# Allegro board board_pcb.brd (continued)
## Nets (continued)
VCC_SYS: C1589.2(B) C1590.1 C1591.1 C1592.1 C1772.1 C1773.2(B) C1880.1 L59.1 Q35.5 Q35.6 Q35.7 Q35.8 R1552.2(B)
VCCD: C1504.2(B) C1505.2(B) U117.24
VDD1V2: C339.2(B) C341.1 C1916.1 LB5.2 U1.N17
VDD_MCU: C197.1 C228.2(B) C229.2(B) C230.2(B) C231.2(B) C271.2(B) C273.2(B) C274.2(B) C282.2(B) C283.2(B) C284.2(B) C285.2(B) C286.2(B) C287.2(B) C288.2(B) C289.2(B) C290.2(B) C342.2(B) C343.2(B) C344.2(B) C345.2(B) C1970.1 C1971.1 C1972.1 C1973.2(B) C1974.2(B) C1975.1 C1976.2(B) C2004.2(B) C2005.2(B) C2006.2(B) C2007.2(B) L63.2 U1.A6 U1.C17 U1.E6 U1.E9 U1.E11 U1.F5 U1.F17 U1.G5 U1.G13 U1.H5 U1.H13 U1.J13 U1.K5 U1.K13 U1.L5 U1.L13 U1.M5 U1.M13 U1.N7 U1.N8 U1.N10 U1.N11 U1.N12 U1.P17 U1.U12
VDD_SDRAM: C1639.2(B) C1818.1 C1819.1 C1820.1 C1821.2(B) C1918.2(B) C1919.2(B) C1920.2(B) C1921.2(B) C1922.2(B) C1923.2(B) C1924.2(B) C1925.2(B) C1926.2(B) C1927.2(B) C1928.2(B) C1929.2(B) C1930.2(B) C1931.2(B) L61.2 U2.A7 U2.B2 U2.B7 U2.C9 U2.D9 U2.E1 U2.F9 U2.L1 U2.L7 U2.M9 U2.N9 U2.P2 U2.P7 U2.R7
VDDA3V3: C1950.1 C1977.1 C1978.2(B) LB8.2 U1.L1
VDDD: C1502.2(B) C1503.2(B) C1506.2(B) R1358.2(B) R1360.2(B) R1368.2(B) R1369.2(B) R1388.2(B) R1389.2(B) R1390.2(B) R1501.1 R1525.1 R1526.1 U117.23(VDDD)
VDDIO3V3_SD: C2001.1 C2002.2(B) LB7.2 U1.F1
AIN_0: J74.3 U134.21
AIN_1: J74.1 U134.20
AIN_2: J74.2 U134.19
BATP: R1519.2(B) R1520.1 R1852.2(B)
BL_KEY: C1910.1 R1744.1 R1856.1 U1.A11 U135.26
BL_REST: C1909.1 R1743.2(B) S6.2 U1.A12 U135.11
BL_RX: R1754.2(B) R1816.1 U135.2
BL_TX: R1753.2(B) R1815.1 U135.1
BOOT0: C1964.1 R1799.1 R1854.1 U1.E8
BOOT1: R1803.1 U1.R6
BQ_AGND: C1653.2(B) C1998.2(B) J85.2 Q39.2(S) R1481.2(B) R1484.2(B) R1500.1 R1503.2(B) R1518.1 R1523.1 R1738.2(B) U133.10 U133.11
BQ_CE_N: R1500.2(B) R1866.2(B) U133.13
BQ_DN: R1510.1 U133.7
BQ_DP: R1510.2(B) U133.6
BQ_INT: R1508.2(B) R1733.2(B) U1.D3
BQ_QON_N: Q39.3 U133.12
BQ_REGN: C1640.1 R1483.1 R1516.1 R1867.2(B) U133.5
BQ_STAT: D134.1(K) U133.1
BQ_TS: C1998.1 J85.1 R1516.2(B) R1518.2(B) R1738.1 R1853.2(B)
CC1: C1499.2(B) D107.1(CATHODE) J73.A5 U117.15
CC2: C1507.2(B) D106.1(CATHODE) J73.B5 U117.14
CE_0: J75.3 J76.1 U134.18
CE_1: J76.6 U134.12
CHARGER_QON: Q39.1 R1503.1 U1.D2
DEBUG_MS_RX: D114.1 J78.14 S8.5
DEBUG_MS_TX: D114.2(C2) J78.12 S8.6
ETH_MDC: U1.M2 U3.24
ETH_MDIO: R1776.2(B) U1.N3
ETH_RMII_CLK: R1778.2(B) R1782.2(B) R1783.2(B) X5.3
ETH_RMII_RXD0: R1774.2(B) U1.T4
ETH_RMII_RXD1: R1775.2(B) U1.U4
ETH_RMII_RXDV: R1777.2(B) U1.R5
ETH_RMII_TX_EN: U1.B9 U3.21
ETH_RMII_TXD0: R1787.1 U1.D9
ETH_RMII_TXD1: R1848.1 U1.U14
ETH_RMII_TXD1-1: R1788.1 U1.D8
FAULT: U1.E5 U117.9
FET_GATE: D97.2 Q22.2 Q22.4 R1381.1 R1495.2(B)
FET_SRC: D97.1(CATHODE) Q22.1 Q22.3(S2) R1495.1
FMC_A0: U1.G4 U2.G8
FMC_A1: U1.G3 U2.G9
FMC_A2: U1.G1 U2.F7
FMC_A3: U1.H4 U2.F3
FMC_A4: U1.J5 U2.G1
FMC_A5: U1.J4 U2.G2
FMC_A6: U1.R7 U2.G3
FMC_A7: U1.P7 U2.H1
FMC_A8: U1.P8 U2.H2
FMC_A9: U1.R9 U2.J3
FMC_A10: U1.T8 U2.G7
FMC_A11: U1.U8 U2.H9
FMC_A12: R1851.1 U1.H16
FMC_A14/FMC_BA0: U1.H14 U2.J7
FMC_A15/FMC_BA1: U1.G14 U2.H8
FMC_D0: U1.P16 U2.R8
FMC_D1: U1.P15 U2.N7
FMC_D2: U1.D13 U2.R9
FMC_D3: U1.E12 U2.N8
FMC_D4: U1.U9 U2.P9
FMC_D5: U1.T9 U2.M8
FMC_D6: U1.P9 U2.M7
FMC_D7: U1.N9 U2.L8
FMC_D8: U1.P10 U2.L2
FMC_D9: U1.R10 U2.M3
FMC_D10: U1.T10 U2.M2
FMC_D11: U1.U10 U2.P1
FMC_D12: U1.R11 U2.N2
FMC_D13: U1.U16 U2.R1
FMC_D14: U1.T17 U2.N3
FMC_D15: U1.T16 U2.R2
FMC_D16: U1.T13 U2.E8
FMC_D17: U1.R13 U2.D7
FMC_D18: U1.P13 U2.D8
FMC_D19: U1.P14 U2.B9
FMC_D20: U1.R14 U2.C8
FMC_D21: U1.D16 U2.A9
FMC_D22: U1.B17 U2.C7
FMC_D23: U1.B16 U2.A8
FMC_D24: U1.A16 U2.A2
FMC_D25: U1.A15 U2.C3
FMC_D26: U1.B15 U2.A1
FMC_D27: U1.C14 U2.C2
FMC_D28: U1.A2 U2.B1
FMC_D29: U1.B3 U2.D2
FMC_D30: U1.E2 U2.D3
FMC_D31: U1.F3 U2.E2
FMC_NBL0: U1.C4 U2.K9
FMC_NBL1: U1.B4 U2.K1
FMC_NBL2: U1.A4 U2.F8
FMC_NBL3: U1.A3 U2.F2
FMC_SDCKE0: R1849.1 U1.N2
FMC_SDCLK: U1.F15 U2.J1
FMC_SDNCAS: U1.D6 U2.K7
FMC_SDNE0: R1835.1 U1.P2 U2.J8
FMC_SDNRAS: U1.T7 U2.J9
FMC_SDNWE: U1.P4 U2.K8(W\E\)
GAUGE_ALCC: R1448.1 R1831.2(B) U1.C3
GAUGE_PULLUP: C511.1 C512.1 Q50.3 R1699.2(B) R1700.2(B) R1831.1
GAUGE_SCL: R1450.1 R1699.1 R1813.1
GAUGE_SDA: R1449.1 R1700.1 R1814.1
GPIO_0: J78.5 U134.6
GPIO_1: J78.10 U134.7
GPIO_2: J78.3 U134.9
GPIO_3: J78.1 U134.10
GPIO_4: J78.8 U134.11
GPIO_5: J78.13 U134.22
GPIO_6: J78.15 U134.23
GPIO_7: J78.7 U134.24
I2C1_SCL: R1812.2(B) R1814.2(B) U1.D5
I2C1_SDA: R1811.2(B) R1813.2(B) U1.D4
ISINK_COARSE: R1368.1 R1370.2(B) U117.5
ISINK_FINE: R1367.1 R1369.1 U117.6
JTCK: J6.3 J56.1 R1838.1 R1843.2(B) U1.B14
JTDI: J56.9 R1839.2(B) U1.A14
JTDO: J56.3 R1842.2(B) U1.C6
JTMS: J6.4 J56.5 R1837.2(B) U1.C15
JTRST: R1840.2(B) R1841.1 U1.B7
LCD_B0: J1.21 J2.21 U1.D11
LCD_B1: J1.22 J2.22 U1.E10
LCD_B2: J1.23 J2.23 U1.D10
LCD_B3: J1.24 J2.24 U1.B10
LCD_B4: J1.25 J2.25 U1.C8
LCD_B5: J1.26 J2.26 U1.B8
LCD_B6: J1.27 J2.27 U1.A8
LCD_B7: J1.28 J2.28 U1.C7
LCD_CLK: J1.30 J2.30 U1.H3
LCD_DE: J1.34 J2.34 U1.D7
LCD_G0: J1.13 J2.13 U1.N14
LCD_G1: J1.14 J2.14 U1.N13
LCD_G2: J1.15 J2.15 U1.M14
LCD_G3: J1.16 J2.16 U1.L14
LCD_G4: J1.17 J2.17 U1.K14
LCD_G5: J1.18 J2.18 U1.J14
LCD_G6: J1.19 J2.19 U1.J15
LCD_G7: J1.20 J2.20 U1.H17
LCD_HSYNC: J1.32 J2.32 U1.H1
LCD_PWM: J1.35 J2.35 U1.E15
LCD_R0: J1.5 J2.5 U1.P5
LCD_R1: J1.6 J2.6 U1.N6
LCD_R2: J1.7 J2.7 U1.P6
LCD_R3: J1.8 J2.8 U1.T6
LCD_R4: J1.9 J2.9 U1.U6
LCD_R5: J1.10 J2.10 U1.U7
LCD_R6: J1.11 J2.11 U1.R12
LCD_R7: J1.12 J2.12 U1.N15
LCD_VSYNC: J1.33 J2.33 U1.H2
LED0: D132.1(K) U1.U5
LINKACT2: J3.11 R1785.1 U3.13
MP1_VCC: C1790.2(B) D112.2 R1604.2(B) U8.9
MS_DWN: C185.1 J78.4 R1740.2(B) S3.2 U1.B11 U134.4
MS_I2CSCL: J78.11 R1755.2(B) U134.25
MS_I2CSDA: J78.9 R1756.2(B) U134.26
MS_RST: C1908.1 J78.6 R1741.2(B) S5.2 U1.C11 U134.5
MS_RX: R1752.2(B) S8.2 S8.4 U134.2
MS_TX: R1751.2(B) S8.1 S8.3 U134.3
NRST: C1965.1 J6.5 R1800.2(B) S11.2 U1.K1
OSC32_IN: C433.2(B) U1.C2 X4.1
OSC32_OUT: C432.2(B) U1.C1 X4.2
OSC_IN: C355.2(B) R84.1 U1.J2 X3.1
OSC_OUT: R32.2(B) R84.2(B) U1.J1
PHY_3V3: C1955.2(B) C1956.1 C1957.1 C1958.2(B) C2000.2(B) C2023.2(B) C2024.2(B) C2025.2(B) LB9.2 R1768.2(B) R1769.2(B) R1770.1 R1773.2(B) R1781.2(B) R1784.2(B) R1785.2(B) R1786.2(B) R1790.1 R1791.1 U3.23 U3.30 U3.31 U3.41 X5.4(VCC)
PHY_INT: R946.2(B) U1.T11
PHY_RESET: R1826.1 U1.B12 U3.40(\R\E\S\E\T\)
PMID: C1695.1 C1696.1 C1697.1 C1698.1 U133.29
POWER_KEY: J86.1 R324.2(B) R325.1 S4.1
POWER_OFF: Q36.1 R1554.2(B) U1.R16
PWR_INT_N: R406.1 U1.R15
QUADSPI_BK1_IO0: R1817.2(B) U1.K4 U77.5
QUADSPI_BK1_IO1: R1819.2(B) U1.L4 U77.2
QUADSPI_BK1_IO2: R1820.2(B) U1.K3 U77.3(W#/VPP/DQ2)
QUADSPI_BK1_IO3: R1818.2(B) U1.K2 U77.7
QUADSPI_BK1_NCS: R898.2(B) U1.G15 U77.1
QUADSPI_CLK: U1.L3 U77.6
RE_0: J75.1 J76.3 U134.16
RE_1: J76.8 U134.14
RX1_N: J73.B10
RX1_P: J73.B11
RX2_N: J73.A10
RX2_P: J73.A11
RX+: J3.3 R1795.2(B) U3.3
RX-: J3.6 R1796.2(B) U3.4
SDIO0_CARD_DETECT: J8.9 R118.2(B) U1.C9
SDIO0_CARD_POWER_EN: R116.1 R119.2(B) U1.U3
SDIO0_CCLK_OUT: J8.5 R281.1
SDIO0_CCMD: J8.3 R1221.1
SDIO0_CDATA0: J8.7 R1222.1
SDIO0_CDATA1: J8.8 R1223.1
SDIO0_CDATA2: J8.1 R1224.1
SDIO0_CDATA3: J8.2 R1225.1
SDIO0_VDD_3.3V: C4.1 C43.1 J8.4 Q1.3 R117.1
SPEEDLED2: J3.10 Q18.3
TP_I2C1_SCL: J1.37 J2.37 R1760.2(B) R1812.1
TP_I2C1_SDA: J1.38 J2.38 R1759.2(B) R1811.1
TP_INT: J1.39 J2.39 R1828.2(B) R1830.2(B) U1.U13
TP_RESET: C1980.1 J1.40 J2.40 R1829.1 U1.P3
TX1_N: J73.A3
TX1_P: J73.A2
TX2_N: J73.B3
TX2_P: J73.B2
TX+: J3.1 R1793.2(B) U3.7
TX-: J3.2(TD-) R1794.2(B) U3.8
UART1_RX: D76.1 J63.3 R1626.2(B) U1.C5
UART1_TX: D76.2(C2) J63.2 U1.B5
UART3_RX: R1865.2(B) S8.8 U1.P12
UART3_TX: S8.7(B6) U1.P11
UART4_RX: R1815.2(B) U1.E17
UART4_TX: R1816.2(B) U1.E16
USB3_DM: D108.1(CATHODE) J73.A7 J73.B7 U1.U15
USB3_DP: D109.1(CATHODE) J73.A6 J73.B6 U1.T15
USB_OTG_ID: R1859.2(B) U1.T14
WE_0: J75.5 J76.2 U134.17
WE_1: J76.7 U134.13(WE_1)
N06481: C1509.1 C1575.1 D96.1(CATHODE) F4.2(P2) Q22.7 Q22.8 R1382.1 R1386.1 R1451.2(B) U117.18
N06955: C1521.1 R1451.1
N07169: C1509.2(B) C1510.2(B) R1381.2(B) R1382.2(B) R1383.2(B)
N07181: R1386.2(B) R1387.2(B) TS1.1
N07533: R1387.1 U117.4
N07661: R1383.1 U117.3
N07823: R1389.1 U117.12
N07951: R1388.1 U117.13
N08069: R1390.1 U117.7
N08149: R1501.2(B) U117.8
N08736: Q2.3 R25.2(B)
N08740: Q2.1 R119.1
N08748: C75.2(B) Q1.1 R25.1 R135.2(B)
N14544: C1641.2(B) U133.4
N14548: C1641.1 L54.2 U133.28
N14620: R1448.2(B) U128.6
N14770: R1450.2(B) U128.4
N14904: R1449.2(B) U128.5
N14944: F1.1 R1446.1 R1520.2(B) U128.8(SENSE-)
N15026: C1642.1 L54.1 U133.26
N15146: C1642.2(B) U133.19
N15862: R1852.1 U133.18
N16110: C1653.1 U133.24
N16190: R1483.2(B) R1484.1 U133.17
N16266: R1481.1 U133.20
N17136: R522.2(B) U1.G17
N26661: C1771.2(B) C1774.1 C1775.1 C1776.1 C1777.1 C1778.2(B) L59.2 R85.1 U8.3(VIN#3) U8.15
N27346: C1595.1 C1597.2(B) C1605.1 C1623.1 C1624.2(B) L50.2 R1611.1 U132.2
N29886: Q35.4 R1706.2(B)
N29984: C1880.2(B) R1705.2(B)
N30034: R1468.1 R1705.1 R1706.1
N30108: C1879.1 R1468.2(B) R1469.2(B) U37.3
N30120: C402.1 R1460.2(B) R1461.1 U37.4(VIN)
N30264: R406.2(B) R1373.1 U37.1
N30390: C413.1 R325.2(B) U37.5
N30402: C595.1 Q36.3 R1552.1 R1553.1 U37.9
N30450: C1485.2(B) U37.8
N34682: R14.2(B) R1739.1 U4.3
N51448: R1747.1 U135.24
N51452: D113.2 R1747.2(B)
N56281: C223.2(B) C354.2(B) C1291.1 C2012.1 C2013.1 L43.2 R1749.1 U26.2
N56325: L10.1 U26.3(SW)
N56705: R86.2(B) R1615.1
N56737: R176.1 U26.7
N56741: R176.2(B) R1615.2(B) R1748.1
N57183: R1749.2(B) U26.8
N60036: D117.1(K) R1751.1
N60157: D118.1(K) R1752.1
N61083: D121.1(K) R1755.1
N61087: D122.1(K) R1756.1
N8840853: R1733.1 U133.21
N8856572: C356.2(B) R32.1 X3.3
N8887240: R281.2(B) U1.C12
N8887299: R1224.2(B) U1.A13
N8887317: R1225.2(B) U1.B13
N8887321: R1223.2(B) U1.E14
N8887325: R1222.2(B) U1.E13
N8887398: R1221.2(B) U1.D12
N8915420: C1945.2(B) U1.U11
N8916004: C1947.2(B) U1.A7
N8924132: R1766.1 U3.48
N8924451: R1767.1 U3.38
N8924569: R1768.1 U3.36
N16774766: R946.1 R1769.1 U3.32
N16774923: R1770.2(B) R1774.1 U3.29
N16774927: R1775.1 U3.28
N16775135: R1773.1 R1776.1 U3.25
N16776183: R1777.1 U3.37
N16776304: R1783.1 U3.42
N16776308: R1778.1 U3.43
N16776812: R1781.1 X5.1
N16777866: R1786.1 U3.11
N16777871: Q18.2(EMITTER) R1784.1 U3.12
N16777887: R1855.2(B) U3.14
N16778460: R1787.2(B) U3.20
N16778536: R1788.2(B) R1848.2(B) U3.19
N16779520: Q18.1 R1855.1
N16781751: J3.9 R1790.2(B)
N16781754: J3.12 R1791.2(B)
N16783015: C1961.2(B) R1793.1 R1794.1
N16783029: C1962.2(B) R1795.1 R1796.1
N16791902: R1797.2(B) R1798.2(B) U1.E7
N16792692: R1854.2(B) S10.1
N16792994: R1856.2(B) S7.1
N16847649: R20.2(B) U4.5
N16850956: D133.2 R1806.2(B)
N16850985: D132.2 R1807.2(B)
N16872883: R1782.1 U1.N4
N16886716: C1946.2(B) U1.D17
N16890832: R1853.1 U133.16
N16908117: R1851.2(B) U2.H3
N16908318: R1849.2(B) U2.J2
N16914135: D74.1(K) R1626.1
N16971823: F1.2(P2) J5.1
N16972859: J5.2(-) J7.1
N16973460: C1904.2(B) Q50.1 R1734.1 R1737.2(B)
N16973494: Q10.3 R1734.2(B)
N16973521: C517.1 Q10.1 R1697.1 R1698.1
N17017170: R50.1 R1673.1 U140.4(Y)
N17017201: R1526.2(B) U140.2
N17038390: D134.2 R1867.1 R1868.2(B)
N17048586: C1875.2(B) D25.2(P2) R1695.1 R1696.1
N17051637: R1863.2(B) R1864.1 U141.3
N17051655: R1862.2(B) U141.5
N17071435: R1868.1 R1869.1
N19175875: C1791.2(B) U8.7
N19175881: R1608.2(B) U8.8
N19175893: C1779.1 L60.1 U8.2 U8.11
N19175909: R1605.1 U8.6
N19176042: R1602.1 R1604.1 U8.5
N19176179: R1599.1 U8.10
N19176181: C1779.2(B) D112.1(K) R1599.2(B)
N19179790: R1608.1 R1609.1
N19180483: C1789.1 R1605.2(B) R1606.1 R1607.1
N19180998: C1789.2(B) R1603.2(B)
N19211433: R85.2(B) R142.1 U8.4
N19540928: R1607.2(B) R1610.1
N19572988: R1611.2(B) U132.8
N19573026: L53.1 U132.3(SW)
N19573046: R1477.1 U132.7
N19573048: R1475.1 R1477.2(B) R1613.1
N19576360: R1612.2(B) R1613.2(B)
N88478500: R1742.1 S5.1
N88479500: R267.1 S3.1
N88497910: R1745.1 S6.1
N167922400: R1802.1 S11.1

Pads without a net: J3 7; J6 6; J56 6 7 8; J73 A8 B8; J75 4; M4 1; NOREF#4 1; NOREF#6 1; NOREF#10 1; NOREF#15 1; NOREF#17 1; NOREF#18 1; U1 A5 A9 A10 D1 D14 D15 E1 E3 E4 F4 F13 F14 F16 H15 K16 K17 L2 L16 L17 M3 M4 M16 M17 N5 R1 R2 R3 R17 T1 T2 T3 T5 U2; U2 E3 E7 H7 K2 K3; U3 16 17 18 22 26 27 34 35 45; U4 6; U26 1; U37 2; U117 10 16 17 20 21; U132 1; U133 14 15; U134 1; U135 3 4 5 6 7 8 9 10 14 15 16 17 18 19 20 21 22 23 25 27 28 29 30 31 32 33 34; U140 1; U141 6

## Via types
v1: diameter 0.559, hole 0.254, TOP to BOTTOM, 1326 vias
v2: diameter 0.406, hole 0.203, TOP to BOTTOM, 328 vias

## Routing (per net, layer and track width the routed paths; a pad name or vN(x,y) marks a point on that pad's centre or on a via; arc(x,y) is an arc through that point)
1V2: length 12.3
  TOP w0.305: U26.5 v1(80,55.37) ; R86.1 78.87,60.1 78.87,62.03 80.59,63.75 v1(81.03,63.75)
  BOTTOM w0.305: v1(80,55.37) 80.64,56.01 82.93,56.01 83.82,56.9 v1(83.82,58.17)
  vias: v1(59.44,75.82) v1(60.2,75.82) v1(60.96,75.82) v1(82.55,63.75) v1(83.82,63.75) v1(83.82,62.48) v1(83.82,61.21)
2V5: length 7.2
  TOP w0.305: v2(54.48,56.01) 54.48,56.13 54.47,56.15 U1.M1
  BOTTOM w0.305: v1(57.28,44.58) 55.85,44.58 R1863.1 ; v2(54.48,56.01) 54.78,55.71 C1952.2 C1951.1 54.36,54.36 54.23,54.48 53.87,54.48 53.85,54.46 v1(53.85,53.72) v1(53.85,52.96)
  vias: v1(57.28,45.47)
3V3: length 85.7
  TOP w0.305: R1759.1 v1(94.74,103) ; R1840.1 40.01,61.98 38.86,60.83 38.86,59.69 v1(39.62,58.93) R1797.1 ; R1817.1 50.93,52.7 v1(51.31,53.09) ; D118.2 v1(32.51,49.91) ; v1(60.71,46.35) 60.02,46.35 58.55,44.88 58.55,41.3 R1612.1 ; D74.2 v1(29.84,11.3) ; D121.2 30.68,35.84 30.99,36.14 v1(30.99,36.47) 31.11,36.6 31.11,39.24 30.1,40.26 D122.2 ; C1904.1 76.96,7.47 R1806.1 ; R1508.1 v1(57.28,15.37) ; 64.14,48.64 63.63,49.15 R1819.1 R1820.1 ; R1753.1 v1(64.9,104.01) ; R1740.1 v1(15.37,65.91) ; D117.2 v1(32.51,51.56) ; R118.1 v1(45.87,89.79) ; R1843.1 v1(50.29,97.16) ; v1(73.79,18.92) 73.94,19.08 R1373.2 ; R1743.1 v1(57.81,90.58) ; R1754.1 v1(64.9,99.69) ; R1837.1 v1(54.99,95.38) ; S10.2 v1(48.56,90.76) ; R1760.1 v1(94.74,101.85) ; C915.1 51.33,47.52 v1(51.69,47.88) ; R1807.1 69.09,47.75 ; D25.1 36.32,49.4 36.04,49.12 C1999.1 36.04,48.16 v1(36.58,47.62) ; v1(52.83,20.19) 53.06,20.42 R1866.1 ; R1741.1 v1(24,65.91) ; R1865.1 29.44,64.16 v1(29.72,63.88) ; R1828.1 v1(85.32,100.23) ; R1800.1 v1(52.96,91.44) ; v1(51.69,47.88) U77.8 ; v1(51.69,47.88) 51.69,47.98 R1818.1 ; R1839.1 v1(57.15,95.38) ; R1842.1 v1(53.34,95.38) ; S7.2 v1(87.25,81.2)
  ART06 w0.508: v1(52.83,20.19) 56.01,17.02 57.02,17.02
  BOTTOM w0.305: 63.25,47.62 63.25,48.44 62.79,48.9 62.79,54.31 64.77,56.29 64.77,62.64 R1835.2 ; LB7.1 46.49,54.36 v1(46.35,54.36) 47.24,53.47 49.64,53.47 LB8.1 50.79,52.57 v1(51.31,53.09) ; R1862.1 58.04,37.47
  vias: v1(5.33,61.09) v1(6.35,61.09) v1(7.49,61.09) v1(7.62,69.47) v1(7.62,68.45) v1(8.64,69.47) v1(8.64,68.45) v1(35.81,9.78) v1(35.81,8.89) v1(36.83,9.78) v1(36.83,8.89) v1(40.13,43.18) v1(40.13,42.42) v1(43.41,90.83) v1(44.2,90.81) v1(49.02,103.5) v1(49.02,102.49) v1(56.64,32.51) v1(57.91,33.91) v1(58.55,35.81) v1(59.31,36.58) v1(60.07,36.58) v1(62.23,46.35) v1(62.61,38.61) v1(63.25,37.21) v1(63.37,87.12) v1(63.37,86.11) v1(63.5,46.35) v1(63.5,45.09) v1(63.5,43.81) v1(63.5,38.61) v1(64.77,46.35) v1(64.77,45.09) v1(64.77,43.81) v1(71.63,47.12) v1(71.63,45.97) v1(71.63,44.7) v1(77.22,6.35) v1(77.22,5.33) v1(78.23,6.35) v1(78.23,5.33)
5V0: length 31.7
  TOP w0.305: R1830.1 v1(85.32,102.87) ; 75.18,45.47 74.93,45.72 74.93,48.39 75.44,48.9 90.17,48.9 93.34,45.72 93.34,41.91 92.94,41.5 R1603.1 92.94,40.39 R1606.2 ; R50.2 42.85,42.47 v1(42.55,42.16) ; R20.1 31.75,34.92 v1(32.13,34.54)
  vias: v1(30.99,34.54) v1(30.99,33.4) v1(32.13,33.4) v1(72.52,37.97) v1(72.52,36.7) v1(73.66,37.97) v1(73.66,36.7) v1(75.18,44.7) v1(75.18,43.69) v1(75.18,42.55) v1(76.2,44.7) v1(76.2,43.69) v1(76.2,42.55) v1(77.47,43.69) v1(77.47,42.55) v1(78.74,43.69) v1(80.01,43.69) v1(92.84,56.77) v1(92.84,55.5) v1(93.98,56.77) v1(93.98,55.5) v1(120.27,104.52) v1(120.27,103.25) v1(121.16,104.52) v1(121.16,103.25) v1(133.86,102.87) v1(133.86,101.6) v1(135,102.87) v1(135,101.6)
5V0_VBUS_0: length 45.8
  TOP w0.152: v1(42.04,44.83) 42.29,44.83 42.85,44.27 R1673.2 ; R522.1 v1(47.37,74.04)
  ART08 w0.114: v1(47.37,74.04) 46.35,74.04 44.13,71.82 37.78,71.82 34.16,68.2 34.16,65.51 36.63,63.04 36.63,61.8 37.08,61.34 37.08,54.48 38.35,53.21 38.35,47.62 39.37,46.61 40.89,46.61 41.4,46.1 41.4,45.47 v1(42.04,44.83)
AGND: length 109.8
  TOP w0.305: R267.2 9.55,64.62 v1(10.03,64.14) ; R1739.2 v1(31.37,41.27) ; R1742.2 v1(16.36,64.39) ; C1908.2 v1(20.55,64.26) ; C185.2 v1(11.91,64.14)
  TOP w0.508: J75.10 21.31,10.41 ; J75.10 20.32,9.42 ; J75.10 20.32,11.4 ; J75.2 15.24,8.86 ; J75.2 15.24,6.88 ; J75.2 16.23,7.87 ; J75.2 14.25,7.87 ; 12.7,1.8 J75.8 ; J75.8 11.71,2.79 ; J75.8 12.7,3.78 ; J75.8 13.69,2.79 ; 19.33,2.79 J75.9 ; J75.9 20.32,1.8 ; J75.9 20.32,3.78 ; J75.9 21.31,2.79 ; J75.7 12.7,11.4 ; J75.7 12.7,9.42 ; J75.7 13.69,10.41 ; J75.7 11.71,10.41
  GND02 w0.508: 11.56,17.51 J76.5 ; J76.5 11.56,19.82 ; J76.5 12.71,18.67 ; J76.5 10.4,18.67 ; 22.85,18.67 J74.4 ; J74.4 25.16,18.67 ; J74.4 24,19.82 ; J74.4 24,17.51 ; 12.94,16.13 J76.4 ; J76.4 15.25,16.13 ; J76.4 14.1,17.28 ; J76.4 14.1,14.97
  ART03 w1.016: v1(33.91,39.62) 33.91,37.72
  ART06 w0.508: 24,17.51 J74.4 ; J74.4 24,19.82 ; J74.4 25.16,18.67 ; J74.4 22.85,18.67 ; J75.2 16.23,7.87 ; J75.2 15.24,6.88 ; J75.2 14.25,7.87 ; J75.2 15.24,8.86 ; 10.4,18.67 J76.5 ; J76.5 11.56,17.51 ; J76.5 11.56,19.82 ; J76.5 12.71,18.67 ; 11.71,10.41 J75.7 ; J75.7 13.69,10.41 ; J75.7 12.7,11.4 ; J75.7 12.7,9.42 ; J75.9 21.31,2.79 ; J75.9 19.33,2.79 ; J75.9 20.32,1.8 ; J75.9 20.32,3.78 ; 11.71,2.79 J75.8 ; J75.8 12.7,3.78 ; J75.8 13.69,2.79 ; J75.8 12.7,1.8 ; J75.10 20.32,11.4 ; J75.10 19.33,10.41 ; J75.10 20.32,9.42 ; J75.10 21.31,10.41 ; J76.4 15.25,16.13 ; J76.4 12.94,16.13 ; J76.4 14.1,14.97 ; J76.4 14.1,17.28
  BOTTOM w0.508: 20.32,1.8 J75.9 ; J75.9 21.31,2.79 ; J75.9 19.33,2.79 ; J75.9 20.32,3.78 ; 11.56,17.51 J76.5 ; J76.5 11.56,19.82 ; J76.5 10.4,18.67 ; J76.5 12.71,18.67 ; 12.94,16.13 J76.4 ; J76.4 15.25,16.13 ; J76.4 14.1,14.97 ; J76.4 14.1,17.28 ; 12.7,1.8 J75.8 ; J75.8 11.71,2.79 ; J75.8 12.7,3.78 ; J75.8 13.69,2.79 ; J74.4 25.16,18.67 ; J74.4 24,19.82 ; J74.4 24,17.51 ; J74.4 22.85,18.67 ; J75.10 21.31,10.41 ; J75.10 20.32,9.42 ; J75.10 19.33,10.41 ; J75.10 20.32,11.4 ; 15.24,6.88 J75.2 ; J75.2 16.23,7.87 ; J75.2 14.25,7.87 ; J75.2 15.24,8.86 ; J75.7 13.69,10.41 ; J75.7 11.71,10.41 ; J75.7 12.7,11.4 ; J75.7 12.7,9.42
  vias: v1(0.89,57.15) v1(0.89,54.61) v1(0.89,52.07) v1(0.89,49.53) v1(0.89,46.99) v1(0.89,44.45) v1(0.89,41.91) v1(0.89,39.37) v1(0.89,36.83) v1(0.89,34.29) v1(0.89,31.75) v1(0.89,29.21) v1(0.89,26.67) v1(0.89,24.13) v1(0.89,21.59) v1(0.89,19.05) v1(0.89,16.51) v1(0.89,13.97) v1(0.89,11.43) v1(0.89,8.89) v1(0.89,6.35) v1(2.54,38.23) v1(2.54,35.69) v1(2.54,33.15) v1(2.54,30.61) v1(2.54,28.07) v1(2.54,25.53) v1(2.54,22.99) v1(2.54,20.45) v1(4.19,15.37) v1(4.19,12.83) v1(4.19,10.29) v1(4.19,7.75) v1(6.48,4.32) v1(7.11,25.4) v1(7.75,0.89) v1(9.02,4.32) v1(9.65,25.4) v1(10.29,0.89) v1(10.41,23.88) v1(10.41,22.48) v1(10.41,20.83) v1(11.56,4.32) v1(11.94,20.83) v1(12.83,0.89) v1(15.37,0.89) v1(17.91,0.89) v1(18.67,19.05) v1(20.45,0.89) v1(21.21,19.05) v1(21.72,8.76) v1(21.97,3.3) v1(22.99,0.89) v1(23.11,6.22) v1(24.26,23.75) v1(24.26,8.76) v1(24.51,3.3) v1(25.53,0.89) v1(25.65,6.22) v1(26.8,23.75) v1(28.19,31.5) v1(28.19,29.21) v1(28.96,48.26) v1(29.08,31.5) v1(29.08,29.21) v1(32,40.39) v1(32.64,48.26) v1(32.64,47.37) v1(32.89,39.62) v1(33.78,46.86) v1(35.18,39.62) v1(35.31,45.47) v1(35.31,44.45) v1(35.31,42.04) v1(35.31,40.77)
AVDD1V8: length 7.3
  TOP w0.254: v1(19.2,79.88) 19.2,80.01 19.52,80.33 U3.2 ; U3.9 v1(16.02,82.57) ; U3.1 v1(20.02,79.88)
  BOTTOM w0.305: C1953.2 16.02,81.92 v1(16.02,82.57) 17.06,82.57 C81.1 ; C1954.2 v1(19.2,79.88)
  vias: v1(25.02,88.52) v1(25.02,87.25) v1(26.29,88.52) v1(26.29,87.25) v1(27.56,88.52) v1(27.56,87.25) v1(28.83,88.52) v1(28.83,87.25) v1(30.1,88.52) v1(30.1,87.25)
GND: length 325.6
  TOP w0.254: J1.36 v1(102.1,104.9) ; J1.29 v1(105.61,104.9) ; v1(11.56,78.61) 11.78,78.84 U3.15 ; v1(43.31,8.89) 44.24,7.95 J73.A1 ; v1(48.21,33.71) 49,32.91 U117.19 50.53,32.91 v1(50.69,32.75) ; U3.33 18.52,74.02 v1(18.8,74.3) ; U3.44 22.72,77.84 v1(22.86,77.98) ; v1(15.24,80.01) 15.52,80.29 U3.10 ; J1.31 v1(104.61,104.9) ; v1(87.88,9.14) 88.13,8.89 U128.7 88.13,6.99 v1(88.39,6.73) ; v1(87.88,9.14) 87.63,9.39 U128.3 87.63,11.18 v1(87.88,11.43) 88.13,11.18 U128.2 88.13,9.39 v1(87.88,9.14) ; D107.2 v1(45,9.99) ; v1(50.67,34.29) 50.55,34.41 U117.22 48.42,34.41 v1(48.21,34.62) ; v1(50.74,8.83) 50.24,8.33 J73.A12 ; U3.39 v1(20.09,75.34)
  TOP w0.305: D76.3 v1(33.66,11.3) ; v1(80.64,14.22) Q10.2 81.41,13.21 81.56,13.36 C517.2 ; U1.N1 55.27,56.24 v2(55.5,56.01) ; v1(52.83,32.64) 53.02,32.64 C1506.1 53.43,33.63 C1502.1 ; C1502.1 C1503.1 ; C1502.1 52.45,33.27 52.01,32.83 v1(52.01,32.64) ; C1503.1 50.98,33.63 50.67,33.93 v1(50.67,34.29) ; C1503.1 50.69,32.88 v1(50.69,32.75) ; U1.H8 v2(50.87,62.85) ; U1.H8 v2(50.87,62.05) ; U1.H8 v2(51.67,62.85) ; R1367.2 46.35,37.62 v1(46.35,37.21) ; U2.L3 v2(71.69,66.43) ; v2(53.27,62.85) U1.L8 v2(53.27,62.05) ; v2(53.27,62.85) U1.K9 ; v2(53.27,62.85) U1.K8 v2(53.27,62.05) ; v2(53.27,62.85) U1.L9 v2(53.27,63.65) ; v2(53.27,62.05) U1.K7 v2(52.47,62.05) ; v2(53.27,62.05) U1.L7 ; v1(89.28,37.57) R1602.2 90.17,36.68 R142.2 v1(90.53,35.31) ; v2(50.87,64.45) U1.H11 v2(51.67,64.45) ; v2(50.87,64.45) U1.H10 ; v2(50.87,64.45) U1.G10 ; v2(50.87,64.45) U1.G11 ; C1485.1 77.66,14.35 v1(76.45,14.35) ; U2.E9 v2(66.89,60.83) ; v1(31.81,3.49) J63.4 v1(31.81,6.48) ; C595.2 78.11,19.56 v1(78.36,19.81) ; C595.2 R1553.2 v1(79.98,19.08) ; C595.2 v1(77.22,19.08) ; C1499.1 v1(50.48,29.27) ; D133.1 76.45,12.1 v1(76.45,13.21) ; v2(51.67,62.85) U1.J8 ; v2(51.67,62.85) U1.J9 ; U1.J8 v2(51.67,62.05) U1.J7 ; U1.J8 v2(52.47,62.85) ; U2.C1 v2(74.08,59.23) ; R1475.2 v1(58.57,37.87) ; C1965.2 v1(52.96,86.74) R1802.2 ; v1(90.17,41.27) R1610.2 91.03,40.59 C1791.1 ; U1.L11 v2(53.27,64.45) ; v2(53.27,64.45) U1.K10 ; v2(53.27,64.45) U1.K11 ; v2(53.27,64.45) U1.L10 ; v1(65.66,27.94) 65.81,27.79 R1869.2 ; v1(83.41,102.87) R1829.2 C1980.2 v1(83.41,100.2) ; C356.1 49.44,50.55 v1(49.89,50.99) ; C1790.1 v1(93.47,38.29) ; C432.1 v1(43.94,52.45) ; U1.R4 v2(57.27,58.85) ; U1.U17 v2(58.87,70.05) ; X3.4 46.33,49.61 C355.1 v1(46.33,51.44) ; U1.J17 v2(52.47,70.05) ; v2(50.87,62.05) U1.H7 ; v2(50.87,62.05) U1.G8 ; v2(50.87,62.05) U1.G7 ; v1(83.19,14.1) R1697.2 C517.2 ; J73.B12 43.96,6.24 43.41,5.69 43.28,5.69 v1(43.05,5.46) ; C1955.1 v1(8.76,74.8) ; R1554.1 81.92,14.99 v1(82.17,15.24) 82.3,15.37 Q36.2 ; R1609.2 v1(92.61,43.15) ; v2(51.67,63.65) U1.H10 ; v2(51.67,63.65) U1.J10 ; v2(51.67,63.65) U1.H9 v2(50.87,63.65) U1.G9 ; v2(51.67,63.65) U1.J9 ; U1.H10 v2(51.67,64.45) ; U1.C13 v2(46.87,66.85) ; v1(48.01,84.84) C1964.2 R1799.2 v1(48.01,83.82) ; v2(52.47,62.85) U1.J9 ; v2(52.47,62.85) U1.K9 ; U1.J9 v2(52.47,63.65) ; U1.T12 v2(58.07,66.05) ; R1838.2 v1(50.29,96.14) ; Q2.2 45.24,83.03 v1(45.24,82.04) R116.2 v1(46.74,81.28) ; U1.G2 v2(50.07,57.25) ; U1.K10 v2(52.47,63.65) ; U1.K10 v2(52.47,64.45) ; U1.A1 v2(45.27,56.45) ; U1.J16 v2(52.47,69.25) ; U1.K9 v2(52.47,63.65) ; C517.2 v1(82.17,14.1) ; J73.B1 50.53,6.24 51.31,5.46 v1(51.44,5.46) ; v1(52.32,38.1) C1505.1 51.47,37.15 51.18,36.86 C1504.1 50.32,36.86 v1(50.29,36.83) ; v2(52.47,63.65) U1.J10 ; R1841.2 R1798.1 v1(39.62,59.94) ; U1.N16 v2(54.87,68.45) U1.M15 ; R1826.2 v1(25.02,69.22) ; C1999.2 36.86,48.92 v1(37.34,49.4) ; R1748.2 v1(78.89,56.67) ; U2.B3 v2(71.69,58.43) ; U2.P3 v2(71.69,68.83) ; U1.J10 v2(51.67,64.45) ; U1.C16 v2(46.87,69.25) ; U2.R3 v2(71.69,69.63) ; v2(51.67,64.45) U1.J11 ; R1359.2 49.53,40.39 v1(49.28,40.64) ; D113.1 v1(78.99,80.26) ; C433.1 v1(39.37,52.45) ; C1507.1 v1(46.42,29.34) ; U2.M1 v2(74.08,67.23) ; U1.R8 v2(57.27,62.05) ; U2.L9 v2(66.89,66.43) ; U1.F2 v2(49.27,57.25) ; C1909.2 v1(58.55,86.74) R1745.2 ; U2.F1 v2(74.08,61.63) ; U77.4 v1(61.72,51.69) ; R1370.1 v1(46.48,40.64) ; U1.G16 v2(50.07,69.25) ; U1.A17 v2(45.27,70.05) ; U1.B2 v2(46.07,57.25) ; U1.P1 v2(56.47,56.45) ; U1.J3 v2(52.47,58.05) ; C1910.2 R1744.2 v1(85.34,90.3) ; C915.2 v1(51.66,46.71) ; U2.B8 v2(68.48,58.43) ; U1.C10 v2(47.67,63.65) ; R1361.1 v1(51.56,40.64) ; C2000.1 v1(31.37,71.12) ; D114.3 v1(24.89,64.77) ; U2.N1 v2(74.08,68.03) ; U2.D1 v2(74.08,60.03) ; U1.U1 v2(58.87,56.45) ; U1.K15 v2(53.27,68.45) ; U2.P8 v2(68.48,68.83) ; U1.B6 v2(46.87,61.25) ; U2.A3 v2(71.69,57.63) ; U1.L15 v2(54.07,68.45) ; R1767.2 v1(24,69.22)
  TOP w0.508: 23.99,95.97 J3.13 ; J3.13 25.4,94.56 ; J3.13 26.81,95.97 ; 13.21,89.1 J3.8 12.18,90.13 ; 130.61,94.49 131.7,94.49 ; 131.7,94.49 131.7,95.58 ; 131.7,94.49 131.7,93.4 ; 131.7,97.03 131.7,98.12 ; 131.7,97.03 130.61,97.03 ; 131.7,97.03 131.7,95.94 ; 9.91,94.56 J3.14 ; J3.14 11.32,95.97 ; J3.14 8.5,95.97
  GND02 w0.508: J2.31 97.23,97.03 ; J2.31 96.14,95.94 ; J2.31 95.05,97.03 ; J2.31 96.14,98.12 ; 98.68,95.94 J2.29 ; J2.29 97.59,97.03 ; J2.29 98.68,98.12 ; J2.29 99.77,97.03 ; J2.36 91.06,95.58 ; J2.36 91.06,93.4 ; J2.36 89.97,94.49 ; J2.36 92.15,94.49
  ART03 w0.508: 51.23,101.09 J56.2 52.07,102.18 ; 57.15,102.18 J56.10 57.99,101.09
  ART06 w0.508: 131.7,94.49 132.79,94.49 ; 131.7,94.49 130.61,94.49 ; 131.7,94.49 131.7,95.58 ; 131.7,94.49 131.7,93.4 ; 12.18,90.13 J3.8 13.21,89.1 ; 130.61,97.03 131.7,97.03 ; 131.7,97.03 131.7,95.94 ; 131.7,97.03 131.7,98.12 ; 131.7,97.03 132.79,97.03 ; 23.99,95.97 J3.13 ; J3.13 26.81,95.97 ; J3.13 25.4,94.56 ; 9.91,94.56 J3.14 ; J3.14 8.5,95.97 ; J3.14 11.32,95.97
  GND07 w0.508: J2.29 99.77,97.03 ; J2.29 98.68,98.12 ; J2.29 97.59,97.03 ; J2.29 98.68,95.94 ; 51.23,101.09 J56.2 52.07,102.18 ; J2.36 92.15,94.49 ; J2.36 91.06,93.4 ; J2.36 89.97,94.49 ; J2.36 91.06,95.58 ; J2.31 96.14,98.12 ; J2.31 97.23,97.03 ; J2.31 96.14,95.94 ; J2.31 95.05,97.03 ; 57.99,101.09 J56.10 57.15,102.18
  GND09 w0.508: 131.7,93.4 131.7,94.49 ; 131.7,94.49 130.61,94.49 ; 131.7,94.49 131.7,95.58 ; 131.7,94.49 132.79,94.49 ; 97.59,97.03 J2.29 ; J2.29 99.77,97.03 ; J2.29 98.68,95.94 ; J2.29 98.68,98.12 ; 96.14,95.94 J2.31 ; J2.31 96.14,98.12 ; J2.31 95.05,97.03 ; J2.31 97.23,97.03 ; 89.97,94.49 J2.36 ; J2.36 91.06,95.58 ; J2.36 91.06,93.4 ; J2.36 92.15,94.49 ; 131.7,97.03 132.79,97.03 ; 131.7,97.03 131.7,95.94 ; 131.7,97.03 131.7,98.12 ; 131.7,97.03 130.61,97.03
  GND09 w1.016: 57.53,23.62 56.26,23.62
  BOTTOM w0.203: v2(48.21,9.27) 48.21,9.79 D108.2 ; v2(46.28,9.27) 46.28,9.79 D109.2
  BOTTOM w0.254: D106.2 49.28,5.21
  BOTTOM w0.305: C1976.1 50.89,69.81 50.32,69.25 v2(50.07,69.25) 49.91,69.09 C1975.2 ; R1803.2 57.76,62.54 v2(57.27,62.05) 56.73,62.59 C282.1 ; v2(71.69,69.63) 71.59,69.72 C1931.1 ; C273.1 50.49,62.85 v2(50.87,62.85) ; R1864.2 54.46,42.42 v1(53.72,42.42) ; C1925.1 74,67.14 v2(74.08,67.23) ; C2025.1 20.02,75.41 v1(20.09,75.34) ; v2(51.67,64.45) 51.67,64.95 C284.1 C283.1 ; v2(46.87,61.25) 46.84,61.21 C1947.1 46.25,60.26 C344.1 46.32,60.2 v2(46.87,59.65) ; C2004.1 56.13,72.14 v2(55.88,72.39) ; C1918.1 74.13,59.98 v2(74.08,60.03) ; C2023.1 18.69,74.19 v1(18.8,74.3) ; C343.1 52.47,65.17 v2(52.47,64.45) ; C285.1 53.27,65.25 v2(53.27,64.45) 53.56,64.45 C345.1 ; C197.2 C345.1 ; C345.1 C231.1 53.78,63.65 v2(53.27,63.65) ; v1(60.86,26.16) 60.5,26.16 C1640.2 ; C290.1 58.71,66.69 v2(58.07,66.05) ; v2(48.26,54.1) 48.26,54.78 C2001.2 ; v2(71.69,58.43) 71.57,58.55 C1921.1 ; v2(50.87,63.65) 50.72,63.5 C286.1 ; v2(66.89,66.43) 66.92,66.46 C1927.1 ; v2(66.89,60.83) 67.04,60.67 C1923.1 C1924.1 ; v2(71.69,68.83) 71.57,68.71 C1930.1 ; C342.1 50,61.34 49.26,61.34 C287.1 ; C342.1 50.16,61.34 v2(50.87,62.05) 51.18,61.73 C2006.1 C342.1 ; v2(68.48,58.43) 68.13,58.08 C1922.1 ; C1977.2 52.17,54.58 v2(52.32,54.74) 52.32,55.46 C1950.2 ; v1(55.24,52.58) 54.74,52.07 C1978.1 ; C2005.1 49.91,65.7 C283.1 ; C1916.2 C341.2 v1(53.09,72.9) ; C1916.2 C339.1 ; C1916.2 v1(53.09,71.88) ; C230.1 54.07,62.05 v2(53.27,62.05) 53.27,61.63 C228.1 C229.1 ; C1929.1 74.04,67.98 v2(74.08,68.03) ; C1946.1 v2(46.86,71.65) ; C1920.1 71.59,57.53 v2(71.69,57.63) ; C2003.1 45.21,56.45 v2(45.27,56.45) ; C274.1 51.8,58.71 v2(52.47,58.05) ; v2(49.15,54.1) C2002.1 ; R1859.1 59.08,70.26 v2(58.87,70.05) ; C2007.1 52.47,61.41 v2(52.47,62.05) ; C1919.1 73.91,59.4 v2(74.08,59.23) ; v1(55.24,53.59) 55.71,54.06 C1951.2 C1952.1 55.71,55.79 v2(55.5,56.01) ; v1(15.75,74.3) 15.98,74.07 C2024.1 ; C283.1 50.13,65.15 C289.1 50.8,64.52 v2(50.87,64.45) ; v2(68.48,68.83) 68.26,69.05 C1928.1 ; C1945.1 60.96,66.22 61.06,66.22 v2(61.09,66.24) ; C1926.1 71.68,66.42 v2(71.69,66.43) ; v2(45.27,70.05) 45.27,70.38 C288.1 ; v2(53.27,62.85) 53.42,62.99 C271.1
  BOTTOM w0.508: 9.91,94.56 J3.14 ; J3.14 11.32,95.97 ; J3.14 8.5,95.97 ; 57.99,101.09 J56.10 57.15,102.18 ; 25.4,94.56 J3.13 ; J3.13 26.81,95.97 ; J3.13 23.99,95.97 ; 51.23,101.09 J56.2 ; 13.21,89.1 J3.8 12.18,90.13
  vias: v1(0.89,103.89) v1(0.89,101.35) v1(0.89,98.81) v1(0.89,96.27) v1(0.89,93.73) v1(0.89,91.19) v1(0.89,88.65) v1(0.89,86.11) v1(0.89,83.57) v1(0.89,81.03) v1(0.89,78.49) v1(0.89,75.95) v1(0.89,73.41) v1(0.89,70.87) v1(0.89,68.33) v1(0.89,65.79) v1(0.89,63.25) v1(0.89,60.71) v1(2.92,100.2) v1(2.92,97.66) v1(2.92,95.12) v1(2.92,92.58) v1(2.92,90.04) v1(2.92,87.5) v1(2.92,84.96) v1(2.92,82.42) v1(2.92,79.88) v1(2.92,77.34) v1(2.92,74.8) v1(2.92,72.26) v1(2.92,69.72) v1(2.92,67.18) v1(2.92,64.64) v1(2.92,62.1) v1(2.92,59.56) v1(4.45,36.96) v1(5.33,64.64) v1(5.33,63.5) v1(5.46,38.86) v1(5.71,41.02) v1(5.84,36.07) v1(5.97,54.61) v1(6.1,45.72) v1(6.22,44.58) v1(6.22,43.56) v1(6.6,64.64) v1(6.6,63.5) v1(6.86,109.09) v1(7.62,72.9) v1(7.62,71.75) v1(7.62,70.61) v1(8.64,72.9) v1(8.64,71.75) v1(9.14,51.05) v1(9.4,109.09) v1(11.94,109.09) v1(14.48,109.09) v1(17.02,109.09) v1(19.56,109.09) v1(22.1,109.09) v1(23.62,75.06) v1(23.62,53.21) v1(24.38,76.71) v1(24.64,109.09) v1(25.15,72.14) v1(26.16,75.95) v1(26.92,50.8) v1(27.18,109.09) v1(27.3,71.12) v1(27.3,0.89) v1(27.56,49.66) v1(27.56,48.9) v1(27.69,101.35) v1(27.69,75.95) v1(28.7,96.65) v1(28.96,105.16) v1(29.59,75.95) v1(29.72,109.09) v1(29.84,71.12) v1(29.97,57.91) v1(30.23,101.35) v1(30.86,31.5) v1(30.86,29.21) v1(31.24,96.65) v1(31.24,57.91) v1(31.24,0.89) v1(31.28,106.77) v1(31.5,105.16) v1(32,31.5) v1(32,29.21) v1(32.51,93.27) v1(32.51,57.91) v1(32.77,101.35) v1(32.77,75.95) v1(32.77,73.53) v1(33.63,92.08) v1(33.78,96.65) v1(33.78,0.89) v1(34.04,105.16) v1(35.05,37.59) v1(35.18,89.66) v1(35.18,88.39) v1(35.43,31.9) v1(35.94,37.59) v1(35.94,36.32) v1(35.94,35.18) v1(36.2,90.81) v1(36.2,89.66) v1(36.2,88.39) v1(36.32,0.89) v1(36.58,79.88) v1(36.58,77.6) v1(36.7,33.02) v1(36.7,31.9) v1(37.34,109.09) v1(37.72,79.88) v1(37.72,78.74) v1(37.72,77.6) v1(37.97,62.36) v1(37.97,57.28) v1(37.97,56.01) v1(37.97,33.02) v1(37.97,31.9) v1(38.61,8.13) v1(38.61,6.86) v1(38.61,5.59) v1(39.24,33.02) v1(39.24,31.9) v1(39.37,50.67) v1(39.62,8.13) v1(39.62,6.86) v1(39.62,5.59) v1(39.75,47.88) v1(39.75,45.85) v1(39.75,44.83) v1(39.88,109.09) v1(40.39,86.61) v1(40.51,33.02) v1(40.51,31.9) v1(40.64,94.49) v1(40.64,91.95) v1(40.64,57.28) v1(40.77,47.88) v1(40.77,44.83) v1(41.27,15.49) v1(41.27,14.48) v1(41.53,0.89) v1(41.66,57.28) v1(41.66,49.02) v1(41.78,33.02) v1(41.78,31.9) v1(42.42,109.09) v1(42.55,40.13) v1(42.55,39.14) v1(42.55,38.25) v1(42.55,15.49) v1(42.55,14.48) v1(43.05,54.1) v1(43.69,97.57) v1(43.81,18.8) v1(43.81,17.91) v1(43.81,17.02) v1(43.81,15.49) v1(43.81,14.48) v1(43.81,0.89) v1(44.78,105.97) v1(44.78,104.78) v1(44.78,102.8) v1(44.83,18.8) v1(44.83,17.91) v1(44.83,17.02) v1(45.09,15.49) v1(45.09,14.48) v1(45.47,48.13) v1(45.72,53.85) v1(45.85,97.57) v1(45.85,0.89) v1(45.95,107.92) v1(45.97,18.8) v1(45.97,17.91) v1(45.97,17.02) v1(47.29,34.62) v1(47.29,33.71) v1(47.75,46.86) v1(48.01,0.89) v1(49.02,101.47) v1(49.02,100.46) v1(49.78,48.9) v1(49.78,46.99) v1(50.29,0.89) v1(52.32,30.61) v1(52.32,29.34) v1(52.32,27.81) v1(52.32,26.92) v1(52.32,25.78) v1(52.58,109.09) v1(52.7,106.43) v1(52.7,103.63) v1(53.21,0.89) v1(53.59,30.61) v1(53.59,25.78) v1(53.72,43.94) v1(54.23,10.29) v1(54.23,9.02) v1(54.23,7.75) v1(54.48,44.96) v1(54.48,41.4) v1(54.61,29.08) v1(54.61,27.94) v1(54.61,26.92) v1(54.74,36.2) v1(54.74,35.18) v1(55.12,109.09) v1(55.12,39.5) v1(55.37,0.89) v1(55.5,32.51) v1(55.5,7.75) v1(55.75,31.37) v1(55.75,30.23) v1(55.75,29.08) v1(55.75,27.94) v1(55.75,26.92) v1(56.13,39.5) v1(57.66,109.09) v1(58.04,18.16) v1(58.04,15.88) v1(58.04,13.59) v1(58.8,19.61) v1(58.8,18.16) v1(58.8,15.88) v1(58.8,13.59) v1(59.82,45.09) v1(59.82,43.81) v1(59.82,42.55) v1(59.82,41.27) v1(59.82,40.13) v1(59.82,38.99) v1(59.82,37.85) v1(60.71,45.09) v1(60.96,37.85) v1(60.96,36.58) v1(60.96,34.92) v1(61.34,23.37) v1(61.98,37.85) v1(61.98,36.58) v1(62.1,23.37) v1(62.74,109.09) v1(62.87,23.37) v1(63.37,84.84) v1(63.37,83.69) v1(64.64,83.69) v1(64.64,30.48) v1(64.64,29.21) v1(64.64,27.94) v1(64.64,26.54) v1(65.28,109.09) v1(65.41,34.54) v1(65.66,30.48) v1(65.66,29.21) v1(65.66,26.54) v1(65.91,83.69) v1(66.04,20.95) v1(66.04,19.68) v1(66.04,18.41) v1(66.04,17.14) v1(66.04,15.88) v1(66.67,34.54) v1(66.8,20.95) v1(66.8,19.68) v1(66.8,18.41) v1(66.8,17.14) v1(66.8,15.88) v1(67.06,54.23) v1(67.06,49.15) v1(67.18,80.64) v1(67.56,0.89) v1(67.69,7.87) v1(67.69,6.73) v1(67.69,5.46) v1(67.94,34.54) v1(68.2,54.23) v1(68.2,51.69) v1(68.2,50.42) v1(68.2,49.15) v1(68.2,47.88) v1(68.2,46.61) v1(68.58,0.89) v1(68.96,7.87) v1(68.96,6.73) v1(68.96,5.46) v1(69.22,38.35) v1(69.22,37.08) v1(69.22,35.81) v1(69.22,34.54) v1(69.87,50.69) v1(70.1,30.1) v1(70.1,28.83) v1(70.1,27.56) v1(70.23,6.73) v1(70.23,5.46) v1(70.48,34.54) v1(70.74,40.26) v1(70.74,38.99) v1(71.5,6.73) v1(71.5,5.46) v1(71.88,0.89) v1(72.01,40.26) v1(72.77,6.73) v1(73.15,13.59) v1(73.15,12.83) v1(73.28,40.26) v1(73.41,0.89) v1(73.66,54.48) v1(73.91,48.9) v1(73.91,47.75) v1(73.91,44.45) v1(73.91,43.69) v1(74.93,0.89) v1(75.06,54.48) v1(75.06,53.34) v1(75.06,52.07) v1(75.06,50.8) v1(75.06,49.53) v1(75.06,16.89) v1(75.06,16) v1(75.06,15.11) v1(75.69,48.13) v1(75.69,47.12) v1(75.95,31.62) v1(76.83,48.13) v1(76.83,47.12) v1(77.22,31.62) v1(77.85,48.13) v1(77.85,47.12) v1(78.23,0.89) v1(78.61,34.16) v1(78.61,32.89) v1(78.61,31.62) v1(78.99,48.13) v1(78.99,47.12) v1(79.38,0.89) v1(79.88,34.16) v1(79.88,32.89) v1(79.88,31.62) v1(79.88,4.57) v1(79.88,3.3) v1(80.01,48.13) v1(80.01,47.12) v1(80.14,62.1) v1(80.14,61.21) v1(80.14,59.94) v1(80.14,58.93) v1(80.14,57.78) v1(80.14,56.64) v1(80.77,4.57) v1(80.77,3.3) v1(81.03,31.62) v1(81.28,56.64) v1(81.28,55.37) v1(81.28,53.72) v1(81.92,0.89) v1(82.04,3.3) v1(82.3,31.62) v1(82.55,56.64) v1(82.55,55.37) v1(82.93,25.02) v1(82.93,23.75) v1(82.93,22.48) v1(82.93,21.21) v1(83.06,109.09) v1(83.57,36.7) v1(83.57,35.43) v1(83.57,34.16) v1(83.57,32.89) v1(83.57,31.62) v1(83.95,41.4) v1(83.95,40.26) v1(83.95,38.99) v1(83.95,37.85) v1(84.2,25.02) v1(84.2,23.75) v1(84.2,22.48) v1(84.2,21.21) v1(84.45,0.89) v1(85.22,41.91) v1(85.22,40.89) v1(85.22,38.99) v1(85.22,37.85) v1(85.34,14.61) v1(85.34,13.34) v1(85.34,12.06) v1(85.6,109.09) v1(85.72,53.34) v1(86.06,71.7) v1(86.06,69.16) v1(86.06,66.62) v1(86.36,14.61) v1(86.36,13.34) v1(86.36,12.06) v1(87,53.34) v1(87,9.65) v1(87,8.64) v1(87,0.89) v1(87.5,14.61) v1(88.14,109.09) v1(88.27,59.69) v1(88.27,53.34) v1(88.77,9.65) v1(88.77,8.64) v1(89.53,59.69) v1(89.53,58.42) v1(89.53,57.15) v1(89.53,55.88) v1(89.53,54.61) v1(89.53,53.34) v1(89.53,0.89) v1(90.68,109.09) v1(90.81,59.69) v1(90.81,53.34) v1(92.08,0.89) v1(92.91,78.05) v1(92.91,75.51) v1(92.91,72.97) v1(92.91,70.43) v1(92.91,67.89) v1(92.91,65.35) v1(92.91,62.81) v1(92.91,60.27) v1(93.22,109.09) v1(94.61,0.89) v1(95.76,109.09) v1(97.16,0.89) v1(98.3,109.09) v1(99.69,0.89) v1(100.84,109.09) v1(100.84,78.23) v1(100.84,75.69) v1(100.84,73.15) v1(100.84,70.61) v1(100.84,68.07) v1(100.84,65.53) v1(100.84,62.99) v1(100.84,60.45) v1(100.84,57.91) v1(100.84,55.37) v1(100.84,52.83) v1(100.84,50.29) v1(100.84,47.75) v1(100.84,45.21) v1(100.84,42.67) v1(100.84,40.13) v1(100.84,37.59) v1(100.84,35.05) v1(100.84,32.51) v1(100.84,29.97) v1(100.84,27.43) v1(100.84,24.89) v1(100.84,22.35) v1(100.84,19.81) v1(100.84,17.27) v1(100.84,14.73) v1(100.84,12.19) v1(100.84,9.65) v1(100.84,7.11) v1(100.84,2.03) v1(102.23,0.89) v1(103.38,109.09) v1(104.78,0.89) v1(105.92,109.09) v1(107.31,0.89) v1(108.46,109.09) v1(109.86,0.89) v1(111,109.09) v1(111.89,79.25) v1(111.89,76.71) v1(111.89,74.17) v1(111.89,71.63) v1(111.89,69.09) v1(111.89,66.55) v1(111.89,64.01) v1(111.89,61.47) v1(111.89,58.93) v1(111.89,56.39) v1(111.89,53.85) v1(111.89,51.31) v1(111.89,48.77) v1(111.89,46.23) v1(111.89,43.69) v1(111.89,41.15) v1(111.89,38.61) v1(111.89,36.07) v1(111.89,33.53) v1(111.89,30.99) v1(111.89,28.45) v1(111.89,25.91) v1(111.89,23.37) v1(111.89,20.83) v1(111.89,18.29) v1(111.89,15.75) v1(111.89,13.21) v1(111.89,10.67) v1(111.89,8.13) v1(111.89,5.59) v1(111.89,3.05) v1(112.39,0.89) v1(113.54,109.09) v1(114.94,0.89) v1(116.08,109.09) v1(117.47,0.89) v1(117.98,105.66) v1(117.98,104.9) v1(118.62,109.09) v1(118.75,77.98) v1(118.75,75.44) v1(118.75,72.9) v1(118.75,70.36) v1(118.75,67.82) v1(118.75,65.28) v1(118.75,62.74) v1(118.75,60.2) v1(118.75,57.66) v1(118.75,55.12) v1(118.75,52.58) v1(118.75,50.04) v1(118.75,47.5) v1(118.75,44.96) v1(118.75,42.42) v1(118.75,39.88) v1(118.75,37.34) v1(118.75,34.8) v1(118.75,32.26) v1(118.75,29.72) v1(118.75,27.18) v1(118.75,24.64) v1(118.75,22.1) v1(118.75,19.56) v1(118.75,17.02) v1(118.75,14.48) v1(118.75,11.94) v1(118.75,9.4) v1(118.75,6.86) v1(118.75,4.32) v1(118.75,1.78) v1(118.87,105.66) v1(118.87,104.9) v1(120.02,0.89) v1(121.16,109.09) v1(122.56,0.89) v1(123.7,109.09) v1(124.71,79.5) v1(124.71,76.96) v1(124.71,74.42) v1(124.71,71.88) v1(124.71,69.34) v1(124.71,66.8) v1(124.71,64.26) v1(124.71,61.72) v1(124.71,59.18) v1(124.71,56.64) v1(124.71,54.1) v1(124.71,51.56) v1(124.71,49.02) v1(124.71,46.48) v1(124.71,43.94) v1(124.71,41.4) v1(124.71,38.86) v1(124.71,36.32) v1(124.71,33.78) v1(124.71,31.24) v1(124.71,28.7) v1(124.71,26.16) v1(124.71,23.62) v1(124.71,21.08) v1(124.71,18.54) v1(124.71,16) v1(124.71,13.46) v1(124.71,10.92) v1(124.71,8.38) v1(124.71,5.84) v1(124.71,3.3) v1(125.09,0.89) v1(126.24,109.09) v1(127.64,0.89) v1(128.78,109.09) v1(129.54,102.87) v1(129.54,101.6) v1(129.54,100.33) v1(129.54,99.06) v1(130.18,0.89) v1(130.56,102.87) v1(130.56,101.6) v1(130.56,100.33) v1(130.56,99.06) v1(131.32,109.09) v1(132.46,87.12) v1(132.46,84.58) v1(132.46,82.04) v1(132.46,79.5) v1(132.46,76.96) v1(132.46,74.42) v1(132.46,71.88) v1(132.46,69.34) v1(132.46,66.8) v1(132.46,64.26) v1(132.46,61.72) v1(132.46,59.18) v1(132.46,56.64) v1(132.46,54.1) v1(132.46,51.56) v1(132.46,49.02) v1(132.46,46.48) v1(132.46,43.94) v1(132.46,41.4) v1(132.46,38.86) v1(132.46,36.32) v1(132.46,33.78) v1(132.46,31.24) v1(132.46,28.7) v1(132.46,26.16) v1(132.46,23.62) v1(132.46,21.08) v1(132.46,18.54) v1(132.46,16) v1(132.46,13.46) v1(132.46,10.92) v1(132.72,0.89) v1(133.86,109.09) v1(136.27,103.5) v1(136.27,100.97) v1(136.27,98.42) v1(136.27,95.89) v1(136.27,93.34) v1(136.27,90.81) v1(136.27,88.27) v1(136.27,85.72) v1(136.27,83.19) v1(136.27,80.64) v1(136.27,78.11) v1(136.27,75.56) v1(136.27,73.03) v1(136.27,70.48) v1(136.27,67.94) v1(136.27,65.41) v1(136.27,62.87) v1(136.27,60.33) v1(136.27,57.78) v1(136.27,55.24) v1(136.27,52.7) v1(136.27,50.16) v1(136.27,47.62) v1(136.27,45.09) v1(136.27,42.55) v1(136.27,40.01) v1(136.27,37.47) v1(136.27,34.92) v1(136.27,32.38) v1(136.27,29.84) v1(136.27,27.3) v1(136.27,24.77) v1(136.27,22.23) v1(136.27,19.68) v1(136.27,17.14) v1(136.27,14.61) v1(136.27,12.06) v1(136.27,9.53) v1(136.27,6.99) v1(139.06,104.78) v1(139.06,102.23) v1(139.06,99.69) v1(139.06,97.16) v1(139.06,94.61) v1(139.06,92.08) v1(139.06,89.53) v1(139.06,87) v1(139.06,84.45) v1(139.06,81.92) v1(139.06,79.38) v1(139.06,76.83) v1(139.06,74.3) v1(139.06,71.75) v1(139.06,69.22) v1(139.06,66.67) v1(139.06,64.14) v1(139.06,61.59) v1(139.06,59.05) v1(139.06,56.52) v1(139.06,53.98) v1(139.06,51.44) v1(139.06,48.9) v1(139.06,46.35) v1(139.06,43.81) v1(139.06,41.27) v1(139.06,38.73) v1(139.06,36.2) v1(139.06,33.66) v1(139.06,31.11) v1(139.06,28.57) v1(139.06,26.04) v1(139.06,23.5) v1(139.06,20.95) v1(139.06,18.41) v1(139.06,15.88) v1(139.06,13.34) v1(139.06,10.79) v1(139.06,8.26) v1(139.06,5.71) v2(42.67,67.94) v2(47.24,7.7) v2(49.78,55.5) v2(57.4,24.13) v2(57.4,23.24) v2(58.04,24.13) v2(58.04,23.24)
GND_SIGNAL: length 10.5
  TOP w0.254: U3.6 17.52,80.26 v1(17.14,79.88) ; U3.47 22.44,79.34 22.73,79.63 v1(22.86,79.63) ; v1(18.29,79.88) 18.02,80.15 U3.5 ; U3.46 v1(22.86,78.84)
  BOTTOM w0.305: v1(17.14,79.88) 17.4,80.14 C81.2 ; C81.2 18.29,79.95 v1(18.29,79.88) 18.39,79.78 C1954.1 ; C81.2 16.29,80.84 C1953.1
  vias: v1(15.58,83.44) v1(17.14,87.76) v1(17.14,86.74) v1(17.58,85.09) v1(17.97,83.44) v1(19.97,85.09) v1(22.29,84.84) v1(28.07,79.63) v1(28.07,78.23) v1(29.21,79.63) v1(29.21,78.23) v1(33.27,79.88) v1(33.27,77.6) v1(34.42,79.88) v1(34.54,77.6)
VBAT: length 15.8
  TOP w0.254: U128.1 88.63,10.91 88.72,11 89.08,11 89.15,10.92
  TOP w0.305: U1.B1 v2(46.07,56.45) ; 89.15,10.92 89.48,10.6 89.48,9.71 89.79,9.4 91.52,9.4 91.82,9.7 R1446.2 ; v1(60.07,12.57) 57.78,12.57 55.75,14.61 55.75,15.85 R1519.1
  BOTTOM w0.305: C2003.2 46.07,55.91 v2(46.07,56.45)
  vias: v1(42.29,55.63) v1(43.43,55.63) v1(60.07,15.88) v1(60.07,13.59) v1(60.83,15.88) v1(60.83,13.59) v1(60.83,12.57) v1(61.59,12.57) v1(67.06,10.92) v1(68.33,10.92) v1(69.47,10.92) v1(70.61,10.92) v1(88.52,16.64) v1(88.52,15.62) v1(88.52,14.61) v1(89.79,16.64) v1(89.79,15.62) v1(89.79,14.61) v1(91.06,16.64) v1(91.06,15.62) v1(91.06,14.61)
VBUS: length 2
  TOP w0.254: v1(49.02,7.09) 48.87,7.09 48.49,6.71 J73.B4 ; J73.B9 45.99,7.02 v1(46.04,7.07)
  vias: v1(42.67,11.68) v1(42.67,10.67) v1(43.94,11.68) v1(43.92,7.09) v1(44.32,8.89) v1(44.68,7.09) v1(45.09,12.7) v1(45.09,11.68) v1(45.21,8.89) v1(48.9,9.91) v1(48.9,8.89) v1(49.78,7.11)
VBUS_MAX: length 4.3
  TOP w0.254: U117.2 48.5,37.2 48.67,37.36
  TOP w0.305: R1358.1 R1359.1 49.53,38.23 48.67,37.36
VBUS_MIN: length 5.1
  TOP w0.254: 49.34,36.77 49,36.43 U117.1
  TOP w0.305: R1360.1 R1361.2 51.56,38.66 51.26,38.35 50.93,38.35 49.34,36.77
VBUS_OUT: length 10.5
  TOP w0.203: U133.9 56.49,24.77 56.26,24.99 v2(56.26,25.45) ; U133.8 57.35,25.33 57.18,25.5 56.97,25.5 56.96,25.49
  TOP w0.254: U117.11 44.84,33.41
  TOP w0.305: C1510.1 45.91,22.99 43.18,22.99 42.42,23.75 42.42,25.78 41.91,26.29
  vias: v1(35.43,28.19) v1(35.43,27.18) v1(35.43,26.16) v1(36.7,28.19) v1(36.7,27.18) v1(36.7,26.16) v1(37.97,28.19) v1(37.97,27.18) v1(37.97,26.16) v1(57.53,32) v1(58.55,33.15) v1(58.55,32) v1(59.56,33.15) v1(59.56,32) v1(59.56,30.61) v1(59.56,28.45) v1(60.33,28.45) v1(60.45,32)
VCC_COMB:
  vias: v1(38.48,44.83) v1(38.48,43.69) v1(61.98,20.7) v1(61.98,19.56) v1(61.98,18.29) v1(61.98,17.02) v1(61.98,15.88) v1(68.58,19.68) v1(68.58,18.41) v1(68.58,17.14) v1(69.85,19.68) v1(69.85,18.41) v1(69.85,17.14) v1(69.98,25.27) v1(69.98,24) v1(69.98,22.73) v1(71.12,25.27) v1(71.12,24) v1(71.12,22.73)
VCC_SYS: length 0.8
  TOP w0.305: C1880.1 77.5,20.85
VCCD: length 3
  TOP w0.254: 50.25,35.65 50.02,35.41 U117.24
  TOP w0.305: 50.25,35.65 50.65,36.04 C1504.2 51.35,35.75 C1505.2
VDD1V2: length 0.6
  TOP w0.305: U1.N17 v2(54.87,70.05)
VDD_MCU: length 42.4
  TOP w0.305: U1.H5 v2(50.87,59.65) U1.G5 ; v2(44.83,60.71) 45.16,60.71 45.3,60.85 U1.A6 ; U1.K13 v2(53.27,66.85) ; U1.J13 v2(52.47,66.85) ; U1.M5 v2(54.87,59.65) ; U1.K5 v2(53.27,59.65) ; U1.N7 v2(55.67,61.25) ; v2(49.53,62.99) 49.28,63.25 U1.E9 ; U1.N11 v2(55.67,65.25) ; U1.H13 v2(50.87,66.85) ; U1.L13 v2(54.07,66.85) ; U1.C17 v2(46.87,70.05) ; U1.E11 49.18,65.15 v2(49.53,65.15) ; v2(49.63,60.86) 49.61,60.88 48.91,60.88 U1.E6 ; U1.F5 v2(49.27,59.65) ; U1.L5 v2(54.07,59.65) ; U1.N8 v2(55.67,62.05) ; U1.N10 v2(55.67,64.45) ; U1.P17 v2(56.07,70.23) ; U1.N12 v2(55.67,66.05) ; U1.M13 v2(54.87,66.85) ; U1.G13 v2(50.07,66.85) ; U1.F17 v2(49.27,70.05) ; U1.U12 v2(58.87,66.05)
  BOTTOM w0.305: v2(50.87,59.65) 50.59,59.65 50.16,60.07 C342.2 49.63,60.77 v2(49.63,60.86) 49.1,60.33 C287.2 49.1,59.82 v2(49.27,59.65) ; v2(50.87,59.65) 50.87,59.93 C2006.2 ; v2(50.87,59.65) 50.88,59.65 C274.2 52.27,60.24 C2007.2 52.7,60.21 v2(53.27,59.65) ; C284.2 51.31,66.41 v2(50.87,66.85) ; v2(58.87,66.05) 59.65,66.83 C290.2 ; v2(56.07,70.23) 56.13,70.3 C2004.2 ; C283.2 50.29,66.62 v2(50.07,66.85) 49.48,66.85 C2005.2 ; C286.2 49.53,63.16 v2(49.53,62.99) 49.53,62.87 49.19,62.52 C273.2 ; C1975.1 48.62,69.39 v2(49.27,70.05) 49.34,69.98 C1976.2 ; v2(55.67,65.25) 55.45,65.02 C345.2 ; v2(44.83,60.71) 45.34,60.2 C344.2 ; C285.2 53.34,66.78 v2(53.27,66.85) v2(54.07,66.85) ; v2(55.67,62.05) 55.79,62.17 C282.2 C271.2 C230.2 55.6,61.98 v2(55.67,62.05) ; v2(55.67,62.05) v2(55.67,61.25) ; v2(54.87,66.85) 55.08,66.64 C197.1 55.66,66.04 v2(55.67,66.05) ; C231.2 55.23,64.01 v2(55.67,64.45) ; C228.2 53.72,60 v2(54.07,59.65) ; C343.2 52.32,66.7 v2(52.47,66.85) ; C288.2 46.87,70.44 v2(46.87,70.05) ; v2(54.87,59.65) 54.74,59.78 C229.2 ; C289.2 49.19,64.81 v2(49.53,65.15)
  vias: v1(63.63,54.23) v1(63.63,53.09) v1(63.63,51.94) v1(64.77,54.23) v1(64.77,53.09) v1(64.77,51.94) v1(65.91,54.23)
VDD_SDRAM: length 7.9
  TOP w0.305: U2.R7 v2(69.28,69.63) ; U2.B7 v2(69.28,58.43) ; U2.P2 v2(72.49,68.83) ; U2.A7 v2(69.28,57.63) ; U2.L1 v2(74.08,66.43) ; U2.N9 v2(66.89,68.03) ; U2.F9 v2(66.89,61.63) ; U2.E1 v2(74.08,60.83) ; U2.B2 v2(72.49,58.43) ; U2.L7 v2(69.28,66.43) ; U2.C9 v2(66.89,59.23) ; U2.P7 v2(69.28,68.83) ; U2.M9 v2(66.89,67.23) ; U2.D9 v2(66.89,60.03)
  vias: v1(70.48,54.48) v1(70.48,53.34) v1(70.48,52.07) v1(71.63,54.48) v1(71.63,53.34) v1(71.63,52.07) v1(71.63,50.8)
VDDA3V3: length 7.4
  TOP w0.305: U1.L1 53.85,56.67 53.85,55.5 v2(54.03,55.32)
  BOTTOM w0.305: LB8.2 51.83,52.07 C1978.2 52.77,52.7 52.98,52.92 C1977.1 53.06,53.54 53.06,55.26 C1950.1 53.85,55.5 v2(54.03,55.32)
VDDD: length 12.7
  TOP w0.254: U117.23 50.96,34.91
  TOP w0.305: R1390.2 43.59,36.98 ; R1368.2 45.47,40.64 ; R1358.2 50.55,40.64 ; R1360.2 52.58,40.64 ; R1388.2 R1389.2 v1(44.2,29.21) ; R1369.2 44.45,40.64
  BOTTOM w0.305: v1(43.69,34.42) 43.69,29.72 v1(44.2,29.21)
VDDIO3V3_SD: length 3.3
  TOP w0.305: U1.F1 v2(49.27,56.45)
  BOTTOM w0.305: v2(49.27,56.45) 49.15,56.33 C2002.2 C2001.1 48.06,55.77 LB7.2
AIN_0: length 15.4
  TOP w0.305: U134.21 27.05,31.37 27.3,31.11 27.3,28.7 28.07,27.94 28.07,20.19 J74.3
AIN_1: length 15.4
  TOP w0.305: J74.1 25.27,17.4 25.27,19.81 27.43,21.97 27.43,27.56 26.16,28.83 U134.20
AIN_2: length 7.6
  TOP w0.305: J74.2 21.97,18.16 21.97,22.86
BATP: length 40.3
  TOP w0.305: v1(55.17,16.08) 55.17,16.61 55.47,16.92 R1519.2 R1852.2
  ART03 w0.305: v1(55.17,16.08) 55.17,15.19 56.13,14.22 68.96,14.22 74.42,8.76 80.52,8.76 86.23,3.05 v1(87.12,3.05)
BL_KEY: length 92.8
  TOP w0.152: U1.A11 44.91,64.85 44.68,64.62 43.54,64.62 v2(42.93,64.01) ; v1(82.42,102.87) 82.42,99.82 83.67,98.58 C1910.1 R1744.1 R1856.1 83.19,89.28 81.82,90.64 U135.26
  BOTTOM w0.152: v2(42.93,64.01) 40.51,64.01 38.99,65.53 38.99,75.06 41.15,77.22 42.67,77.22 44.17,78.71 44.17,80.44 45.06,81.33 45.64,81.33 46.35,82.04 49.53,82.04 52.32,84.84 52.32,88.27 55.37,91.31 55.75,91.31 67.56,103.12 82.17,103.12 v1(82.42,102.87)
BL_REST: length 51.1
  TOP w0.152: U135.11 65.65,87.64 62.53,90.76 S6.2 60.53,90.76 59.54,89.76 R1743.2 C1909.1 58.06,88.67 57.66,88.27 57.66,83.06 57.15,82.55 53.59,82.55 50.36,79.31 50.36,78.8 49.91,78.36 47.37,78.36 v1(46.74,78.99) ; v2(43.94,65.68) 43.98,65.65 U1.A12
  BOTTOM w0.152: v1(46.74,78.99) 46.61,78.99 41.15,73.53 41.15,67.01 42.47,65.68 v2(43.94,65.68)
BL_RX: length 3.9
  TOP w0.152: R1816.1 63.93,101.37 R1754.2 66.14,101.37 66.37,101.14 U135.2
BL_TX: length 3.9
  TOP w0.152: R1815.1 63.93,102.34 R1753.2 66.01,102.34 66.32,102.64 U135.1
BOOT0: length 34.4
  TOP w0.152: v1(45.21,80.14) 45.8,80.72 47.04,80.72 47.35,81.03 47.35,81.79 46.33,82.8 R1799.1 C1964.1 R1854.1 ; U1.E8 v2(48.47,62.85)
  BOTTOM w0.152: v1(45.21,80.14) 45.97,79.38 45.97,78.87 40.77,73.66 40.77,66.73 42.29,65.2 45.89,65.2 45.95,65.26 47.08,65.26 47.49,64.85 47.92,64.85 48.07,64.69 48.07,64.27 48.47,63.87 v2(48.47,62.85)
BOOT1: length 3.8
  TOP w0.152: U1.R6 v2(57.27,60.45)
  BOTTOM w0.152: v2(57.27,60.45) 57.66,60.83 58.29,60.83 58.47,61.01 58.47,62.28 58.57,62.38 R1803.1
BQ_AGND: length 7.9
  TOP w0.305: R1484.2 53.64,18.14 C1998.2 v1(53.62,17.27)
  BOTTOM w0.305: v1(53.62,17.27) 53.62,18.19 55.5,20.07 C1653.2 R1481.2
  vias: v1(51.05,22.23) v1(51.05,21.21) v1(51.05,19.94) v1(51.05,18.67) v1(51.05,17.4) v1(51.05,16.13) v1(52.45,14.73) v1(53.85,24.64) v1(53.98,13.21) v1(54.74,24.64) v1(55.37,11.81) v1(55.63,24.64) v1(56.64,10.54) v1(57.02,0.89) v1(57.15,4.83) v1(57.53,8) v1(57.53,6.73) v1(58.8,8) v1(58.8,6.73) v1(60.07,9.14) v1(60.07,8) v1(60.07,6.73) v1(60.33,0.89) v1(61.34,6.73) v1(61.85,0.89) v1(63.37,0.89) v1(63.75,9.65) v1(63.75,6.73) v1(63.75,4.83) v1(64.9,8.51) v1(65.91,6.73) v1(65.91,4.83)
BQ_CE_N: length 4.7
  TOP w0.203: R1500.2 53.34,21.21 53.37,21.23 R1866.2 54.25,21.23 56.19,23.17 U133.13
BQ_DN: length 2.8
  TOP w0.13: v2(57.02,26.67) 57.16,26.53 57.16,26.25 57.48,25.93 57.68,25.93 57.78,25.83 57.78,25.72 57.75,25.68 U133.7
  BOTTOM w0.13: R1510.1 57.12,27.18 57.12,26.77 v2(57.02,26.67)
BQ_DP: length 2.8
  TOP w0.13: U133.6 58.15,25.68 58.11,25.72 58.11,25.97 57.82,26.26 57.61,26.26 57.49,26.39 57.49,26.5 v2(57.66,26.67)
  BOTTOM w0.13: R1510.2 57.45,27.2 57.45,26.88 v2(57.66,26.67)
BQ_INT: length 64.4
  TOP w0.152: v1(42.8,47.62) 44.49,49.32 44.49,51.7 46.99,54.2 46.99,54.99 47.67,55.67 47.67,58.05 U1.D3 ; R1733.2 R1508.2 56.95,16.92 56.64,16.61 56.64,15.62 v1(56.39,15.37)
  ART08 w0.114: v1(56.39,15.37) 56.39,15.62 57.72,16.95 58.61,16.95 59.94,18.29 59.94,24.64 59.03,25.55 57.3,25.55 56.52,26.34 50.5,26.34 48.44,28.4 48.44,31.27 46.69,33.02 46.69,35.18 43.69,38.18 43.69,41.1 45.59,43 45.59,46.35 44.32,47.62 v1(42.8,47.62)
BQ_QON_N: length 1.8
  TOP w0.203: U133.12 54.94,23.57 Q39.3
BQ_REGN: length 36.8
  TOP w0.203: v2(58.29,26.67) 58.55,26.42 U133.5
  TOP w0.305: v1(58.93,11.68) 59.18,11.43 61.75,11.43 R1516.1 ; v1(66.67,30.48) 68.35,30.48 R1867.2
  ART08 w0.305: v2(57.4,22.48) 57.4,22.12 57.91,21.62 57.91,19.18 55.75,17.02 55.75,14.86 v1(58.93,11.68)
  BOTTOM w0.305: v2(57.4,22.48) 57,22.89 R1483.1 56.64,24.38 57.78,25.53 C1640.1 58.29,25.58 v2(58.29,26.67) 58.29,27.18 58.8,27.69 60.71,27.69 64.26,31.24 66.04,31.24 66.67,30.61 v1(66.67,30.48)
